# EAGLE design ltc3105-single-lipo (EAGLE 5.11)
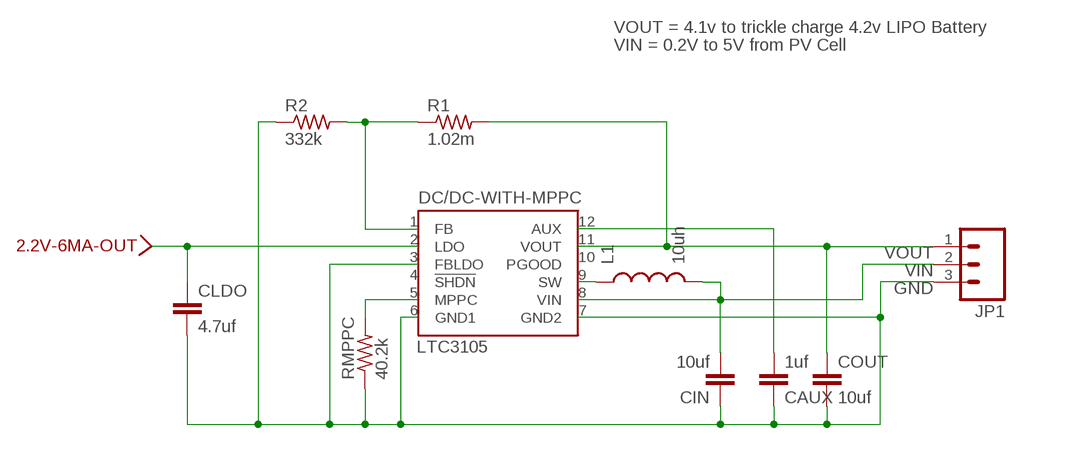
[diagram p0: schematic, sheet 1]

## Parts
2.2V-6MA-OUT  WIREPAD-SMD-SMALL-NAMED  [WIREPAD-SMD-SMALL]
CAUX  1uf  C-EUC1206  [C1206]
CIN  10uf  C-EUC1206  [C1206]
CLDO  4.7uf  C-EUC1206  [C1206]
COUT  10uf  C-EUC1206  [C1206]
DC/DC-WITH-MPPC  LTC3105  [12MSOP]
JP1  M03PTH  [1X03]
L1  10uh  INDUCTOR1210  [1210]
R1  1.02m  R-US_R0805  [R0805]
R2  332k  R-US_R0805  [R0805]
RMPPC  40.2k  R-US_R0805  [R0805]

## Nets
GND: CAUX.1 CIN.1 CLDO.2 COUT.2 DC/DC-WITH-MPPC.3(FBLDO) DC/DC-WITH-MPPC.6(GND1) DC/DC-WITH-MPPC.7(GND2) JP1.3 R2.1 RMPPC.1
N$1: DC/DC-WITH-MPPC.9(SW) L1.1
N$2: DC/DC-WITH-MPPC.5(MPPC) RMPPC.2
N$4: 2.2V-6MA-OUT.1 CLDO.1 DC/DC-WITH-MPPC.2(LDO)
N$5: DC/DC-WITH-MPPC.1(FB) R1.1 R2.2
N$6: CAUX.2 DC/DC-WITH-MPPC.12(AUX)
VIN: CIN.2 DC/DC-WITH-MPPC.8(VIN) JP1.2 L1.2
VOUT: COUT.1 DC/DC-WITH-MPPC.11(VOUT) JP1.1 R1.2
Unconnected: DC/DC-WITH-MPPC.4(!SHDN) DC/DC-WITH-MPPC.10(PGOOD)

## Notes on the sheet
- VOUT = 4.1v to trickle charge 4.2v LIPO Battery
- VIN = 0.2V to 5V from PV Cell

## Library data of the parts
2.2V-6MA-OUT = trl:WIREPAD-SMD-SMALL-NAMED
CAUX CIN CLDO COUT = rcl:C-EU: CAPACITOR, European symbol
DC/DC-WITH-MPPC = trl:LTC3105
JP1 = SparkFun:M03: Header 3 Standard 3-pin 0.1" header. Use with straight break away headers (SKU : PRT-00116), right angle break away headers (PRT-00553), swiss pins (PRT-00743), machine pins (PRT-00117), and female headers (PRT-00115). Molex polarized connector foot print use with SKU : PRT-08232 with associated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
L1 = SparkFun:INDUCTOR: Inductors
R1 R2 RMPPC = resistor:R-US_: RESISTOR, American symbol

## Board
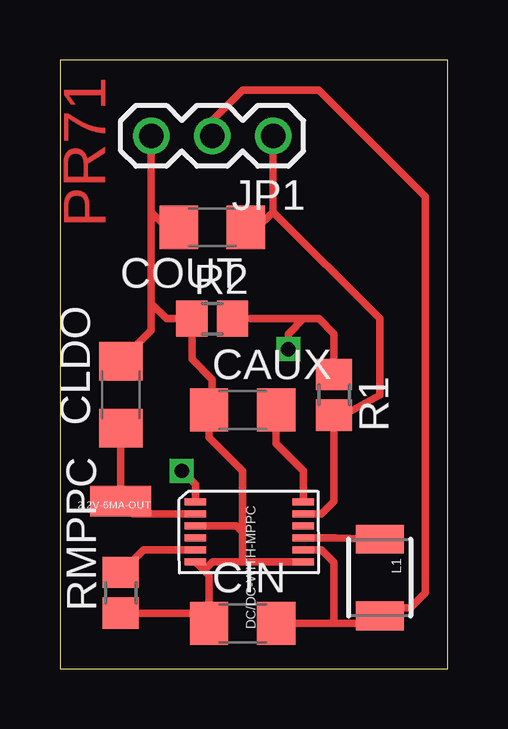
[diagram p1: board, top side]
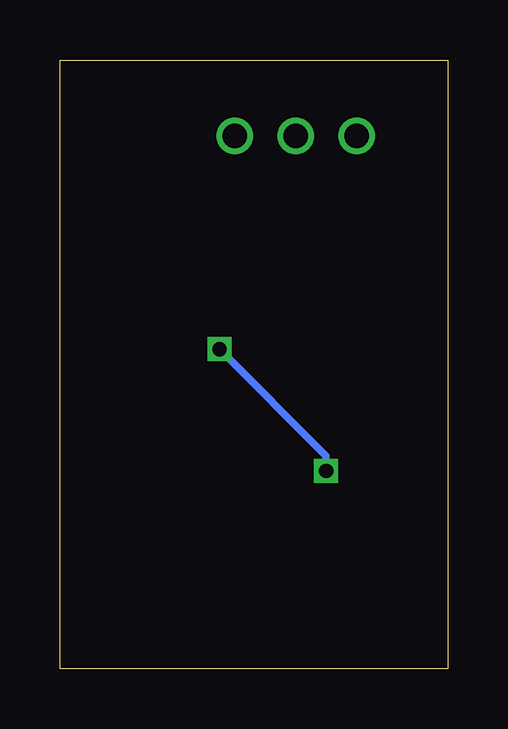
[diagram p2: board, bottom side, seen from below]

Size 16.18 x 25.39 mm. Coordinates in mm from the lower left corner, seen from the top.
Outline: 0,0 16.18,0 16.18,25.39 0,25.39 0,0
Copper layers (1*16): Top 0.035mm / dielectric 1.5mm / Bottom 0.035mm
Design rules "default": minimum track width 10mil, minimum drill 24mil, track to track 8mil, track to pad 8mil, pad to pad 8mil, via to via 8mil, smd to smd 8mil, copper to edge 40mil, drill to drill 8mil, minimum pad ring 10mil, minimum via ring 8mil, stop-mask expansion 4mil, vias tented up to drill 0mil, thermal gap 10mil

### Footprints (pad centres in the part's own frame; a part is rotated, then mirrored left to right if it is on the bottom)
WIREPAD-SMD-SMALL = smd 2.54 x 1.27: 1 0,0
C1206 = smd 1.6 x 1.8: 1 -1.4,0; 2 1.4,0
12MSOP = smd 0.3 x 0.9: 1 -1.25,-1.97; 2 -0.75,-1.97; 3 -0.25,-1.97; 4 0.25,-1.97; 5 0.75,-1.97; 6 1.25,-1.97; 7 1.25,2.53; 8 0.75,2.53; 9 0.25,2.53; 10 -0.25,2.53; 11 -0.75,2.53; 12 -1.25,2.53
1X03 = drill 1.016 round: 1 0,0; 2 2.54,0; 3 5.08,0
1210 = smd 1.2 x 2: 1 -1.6,0; 2 1.6,0
R0805 = smd 1.3 x 1.5: 1 -0.85,0; 2 0.85,0

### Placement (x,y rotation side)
2.2V-6MA-OUT  2.54,6.99 180 top
CAUX  7.62,10.79 0 top
CIN  7.62,1.91 0 top
CLDO  2.54,11.43 90 top
COUT  6.35,18.41 180 top
DC/DC-WITH-MPPC  7.62,5.71 270 top
JP1  8.89,22.23 180 top
L1  13.34,3.81 270 top
R1  11.43,11.43 270 top
R2  6.35,14.61 0 top
RMPPC  2.54,3.17 90 top

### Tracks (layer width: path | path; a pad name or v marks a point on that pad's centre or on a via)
GND
  Top 0.305: 6.01,4.11 6.22,3.9 CIN.1 5.8,2.33 RMPPC.1 | 6.01,4.11 DC/DC-WITH-MPPC.6 | 7.62,4.46 6.37,4.46 6.01,4.11 | 7.62,4.46 DC/DC-WITH-MPPC.7 | DC/DC-WITH-MPPC.3 7.37,5.96 7.62,5.71 | 7.62,4.46 7.62,5.71 | 7.62,5.71 7.62,8.26 6.22,9.65 CAUX.1 6.35,10.93 6.35,12.06 5.5,12.91 R2.1 4.45,14.61 3.81,15.24 | 3.81,15.24 3.81,14.1 CLDO.2 | 3.81,15.24 3.81,19.05 | 3.81,19.05 JP1.3 | COUT.2 4.45,18.41 3.81,19.05
N$1
  Top 0.305: DC/DC-WITH-MPPC.9 11.48,5.46 L1.1
N$2
  Top 0.305: DC/DC-WITH-MPPC.5 3.48,4.96 RMPPC.2
N$4
  Top 0.305: DC/DC-WITH-MPPC.2 3.06,6.46 2.2V-6MA-OUT.1 CLDO.1
N$5  (via drill 0.6)
  Top 0.305: DC/DC-WITH-MPPC.1 5.65,7.68 v5.08,8.26 | 10.16,14.61 R2.2 | 10.16,14.61 10.79,14.61 11.43,13.97 R1.1 | v9.53,13.34 9.53,13.97 10.16,14.61
  Bottom 0.305: v5.08,8.26 5.08,8.89 v9.53,13.34
N$6
  Top 0.305: CAUX.2 9.02,9.39 10.16,8.26 10.16,6.97 DC/DC-WITH-MPPC.12
VIN
  Top 0.305: CIN.2 11.43,1.91 | 11.43,1.91 13.03,1.91 L1.2 13.66,2.54 14.61,2.54 15.24,3.17 15.24,19.68 10.79,24.13 7.62,24.13 6.35,22.86 JP1.2 | DC/DC-WITH-MPPC.8 10.91,4.96 11.43,4.45 11.43,1.91
VOUT
  Top 0.305: DC/DC-WITH-MPPC.11 10.91,6.46 11.43,6.99 R1.2 11.85,10.58 13.34,11.43 13.34,14.61 8.89,19.05 | COUT.1 8.26,18.41 8.89,19.05 | 8.89,19.05 JP1.1

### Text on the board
Top: PR71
